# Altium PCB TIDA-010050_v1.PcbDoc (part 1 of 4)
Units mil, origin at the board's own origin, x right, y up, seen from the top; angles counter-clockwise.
Board outline 2060.77 x 1300 mil, 4 copper layers (Top Layer, signal1, signal2, Bottom Layer), stack 23.6 mil thick; 58 components, 30 nets, 158 pads, 41 vias.
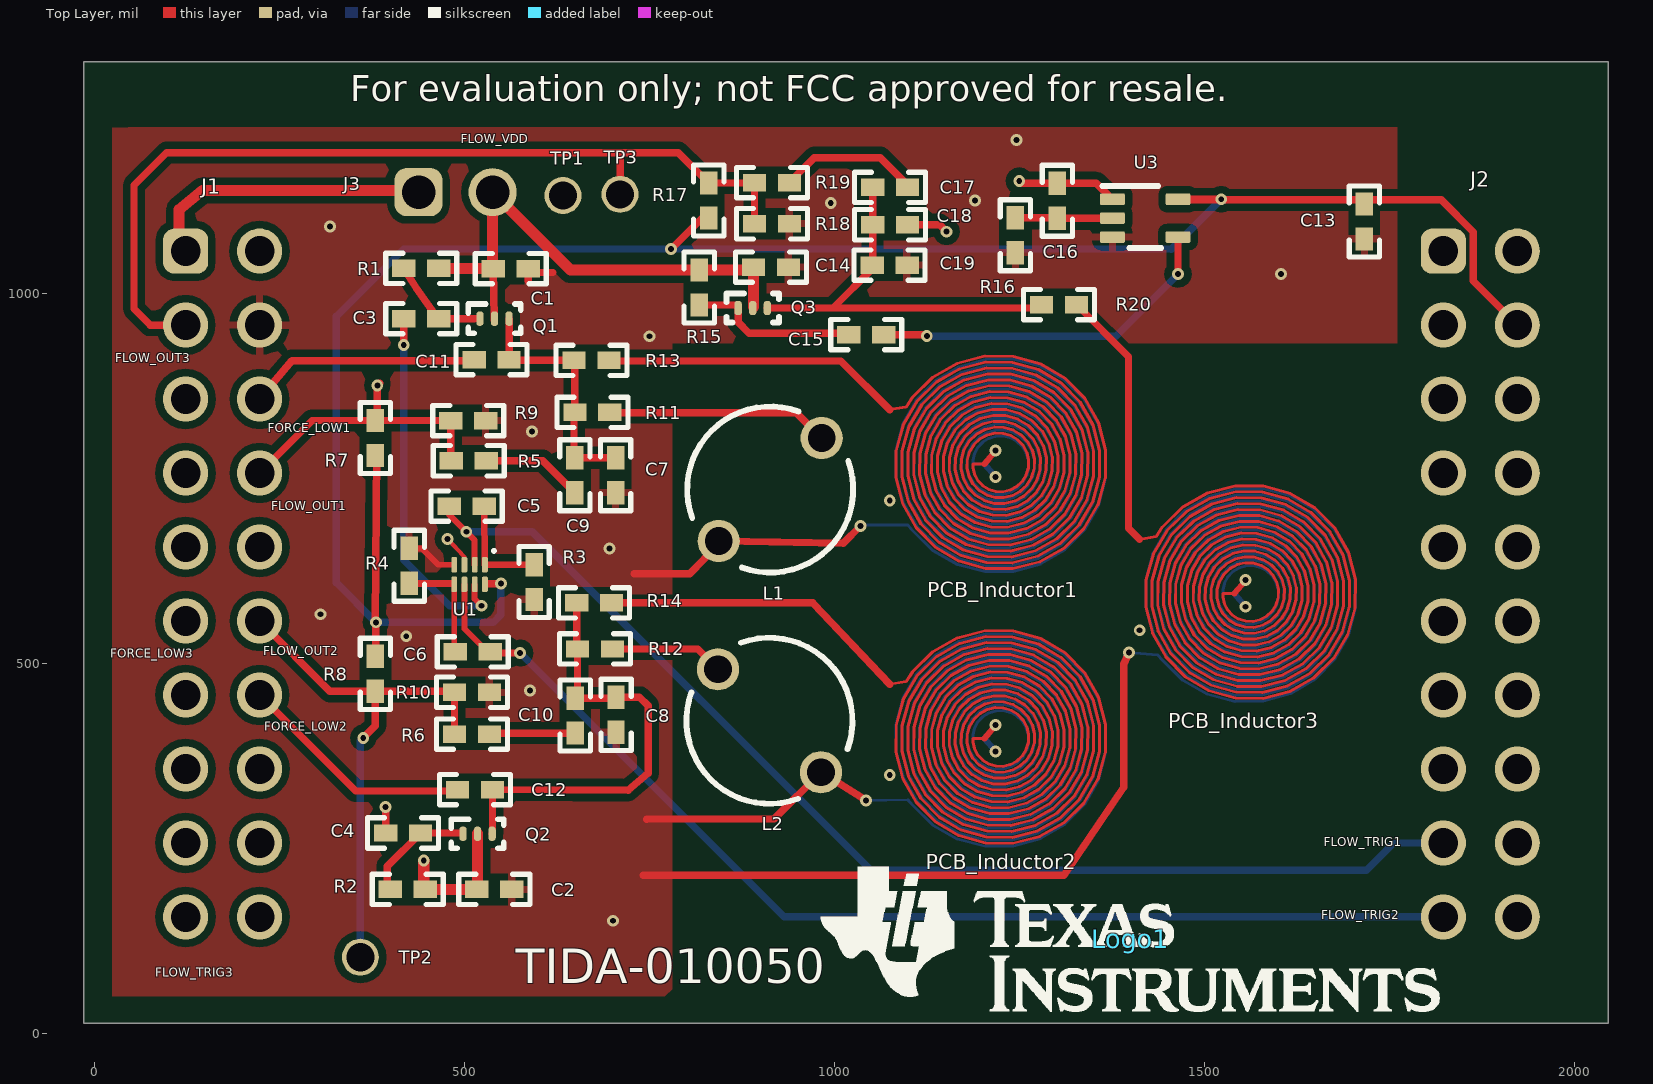
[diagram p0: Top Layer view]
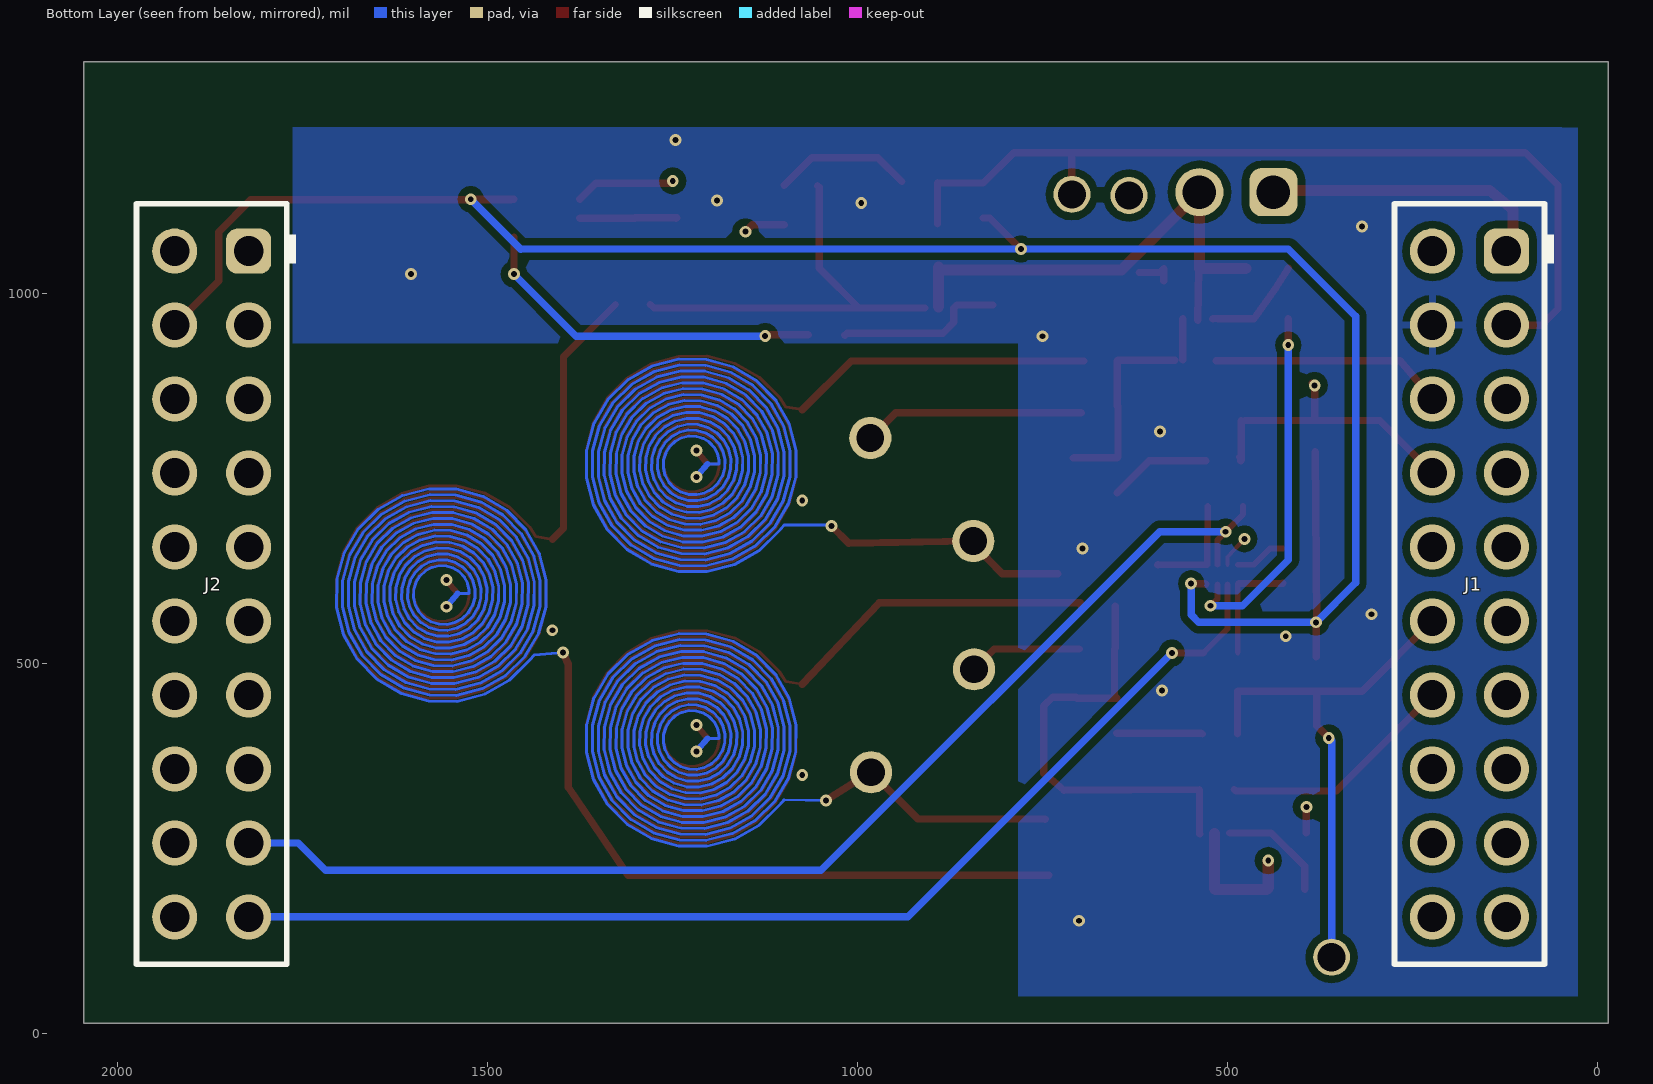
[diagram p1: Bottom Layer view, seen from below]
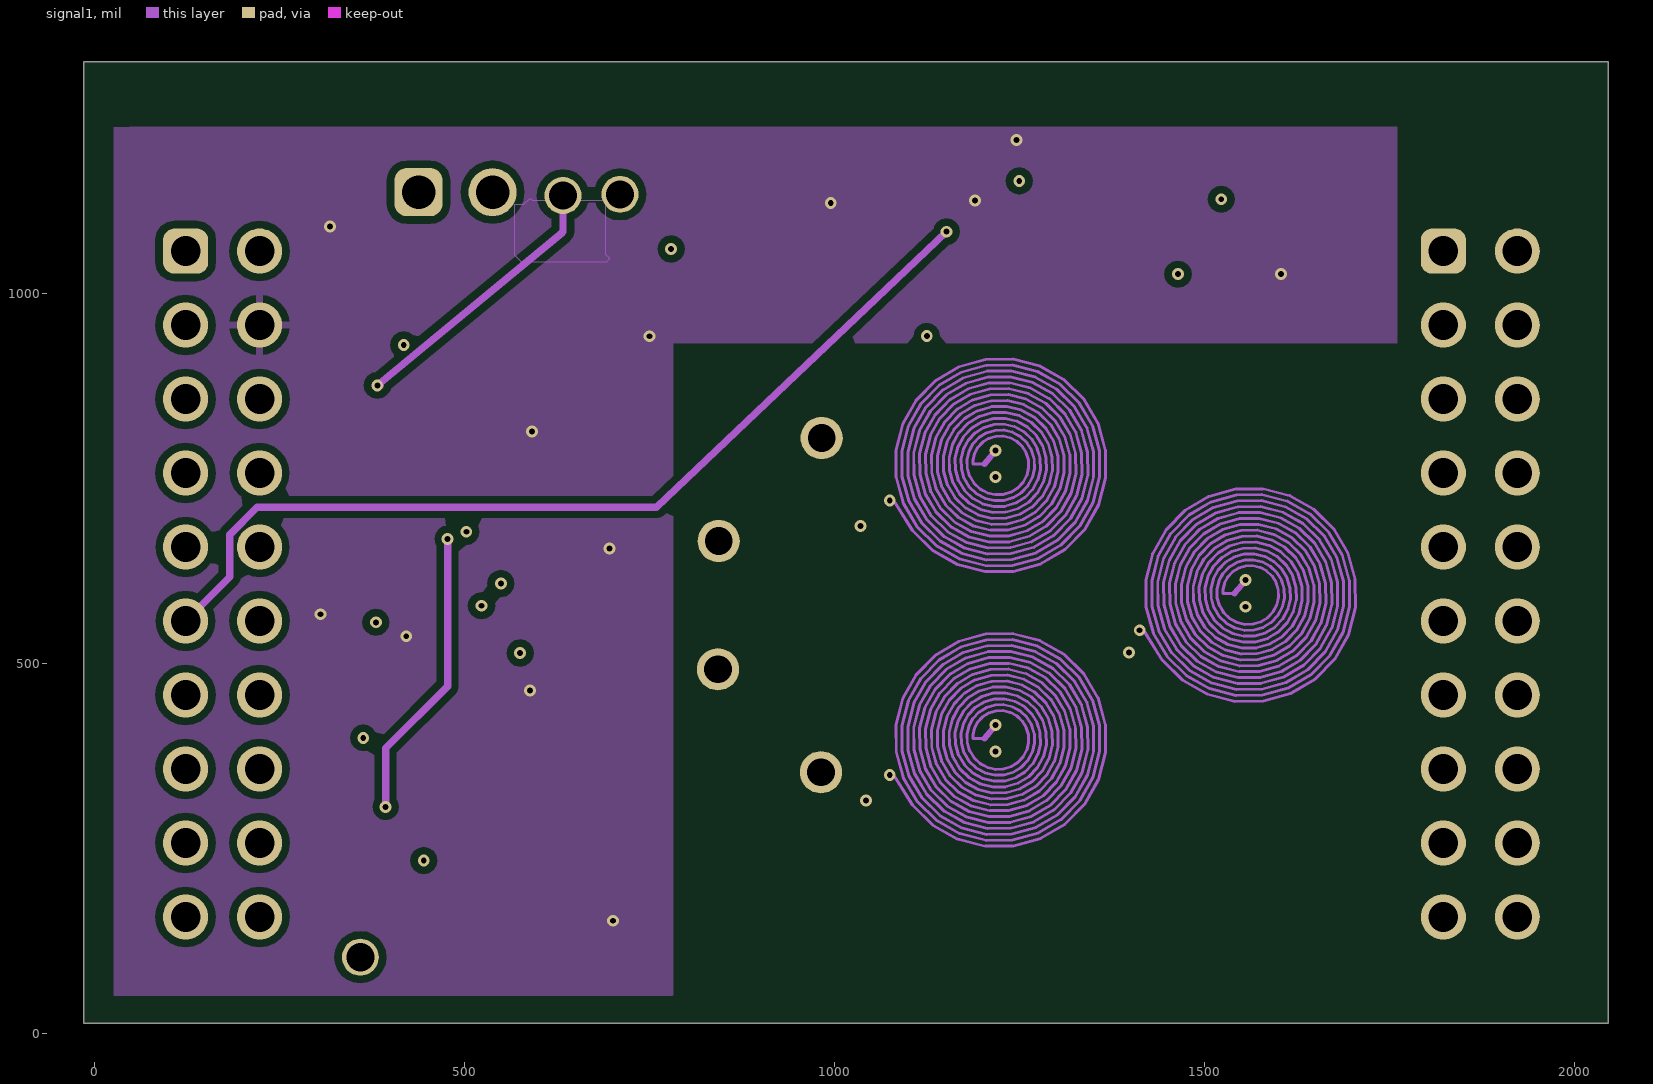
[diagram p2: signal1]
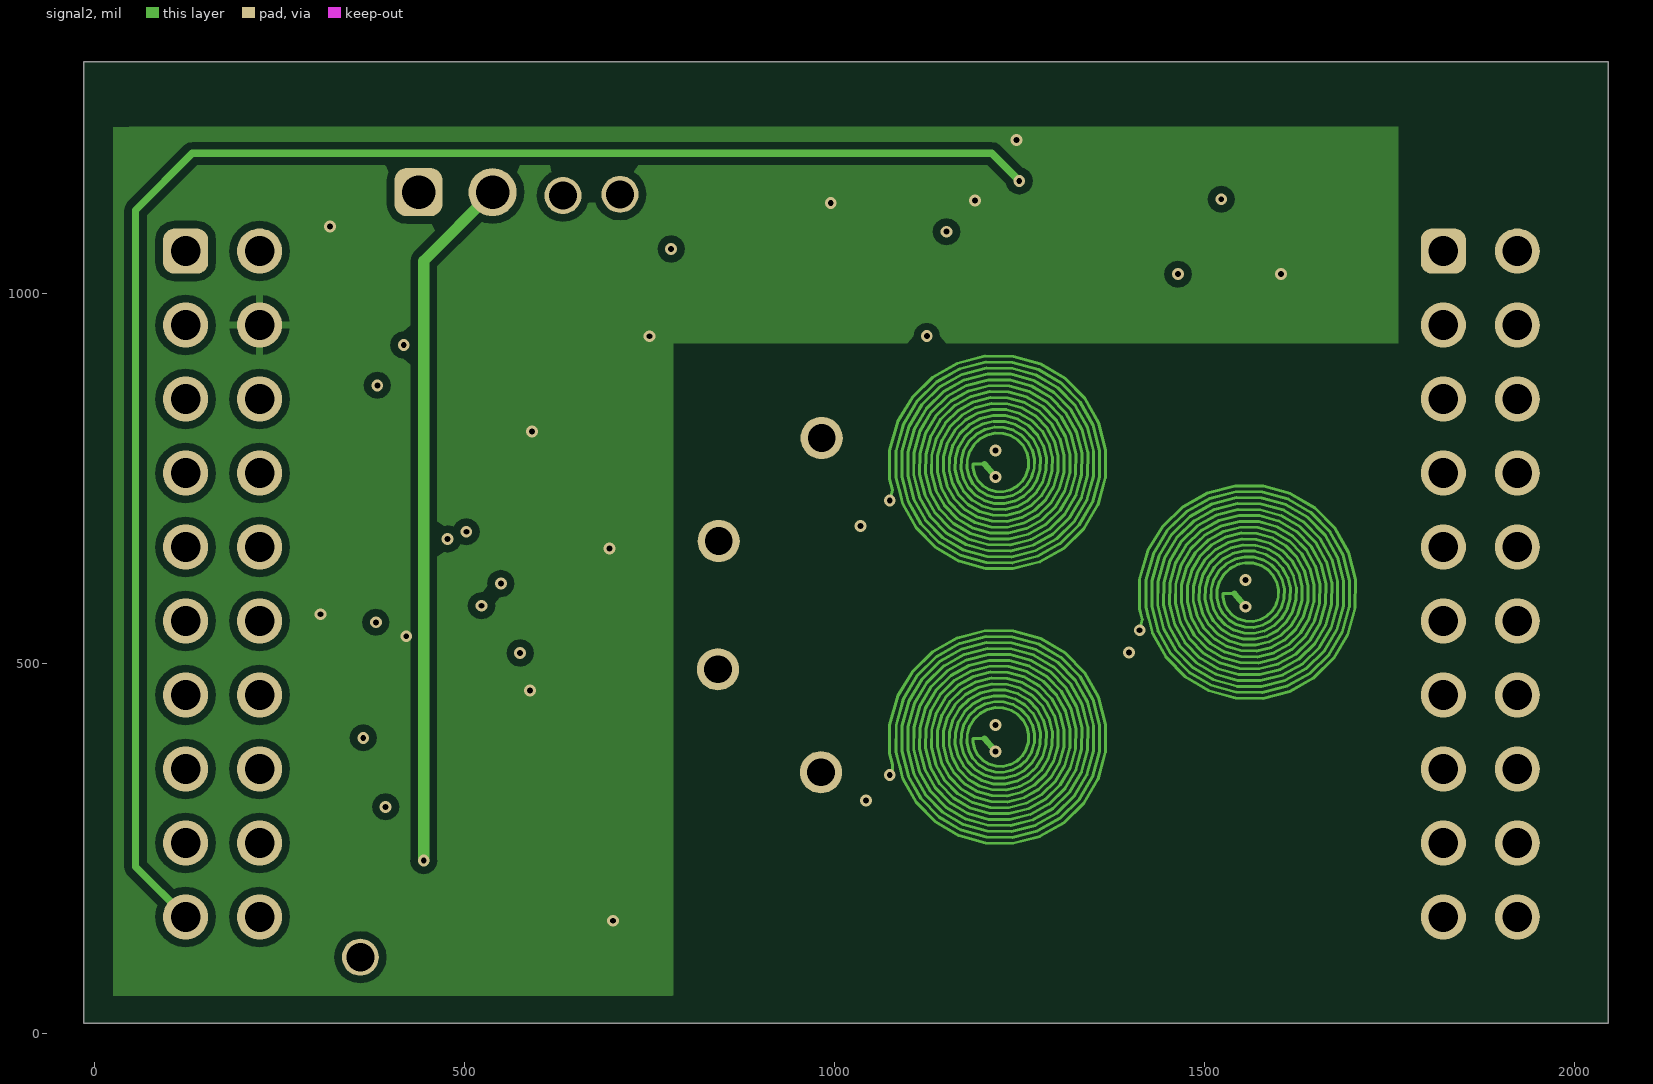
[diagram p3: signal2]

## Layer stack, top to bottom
Top Solder: solder mask 0.4, Solder Resist, Dk 3.5
Top Layer: signal copper 1.4
Dielectric 1: prepreg 5, FR-4, Dk 4.2
signal1: signal copper 1.4
Dielectric 2: core 8, FR-4, Dk 4.2
signal2: signal copper 1.4
Dielectric 3: prepreg 5, FR-4, Dk 4.2
Bottom Layer: signal copper 1.4
Bottom Solder: solder mask 0.4, Solder Resist, Dk 3.5

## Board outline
-15,13 2045.77,13 2045.77,1313 -15,1313

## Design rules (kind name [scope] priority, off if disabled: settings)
AcuteAngle [All] p1: minimum=4.50000000000000E+0001 checktracksonly=FALSE
AssemblyTestPointUsage [All] p1: valid=2
BoardOutlineClearance BoardOutlineClearance_MountingHoles [OnCopper and InComponentClass('Mounting Holes')] p1: gap=39.37 ignorepadtopadclearanceinfootprint=FALSE
BoardOutlineClearance BoardOutlineClearance_Poly [OnCopper and IsPoly] p2: gap=25 ignorepadtopadclearanceinfootprint=FALSE
BoardOutlineClearance [OnCopper and Not InComponentClass('Logo') and not InComponentClass('FiducialMark') and not InRegion(1000,500,4000,800) and not InPoly] p3: gap=30 ignorepadtopadclearanceinfootprint=FALSE
Clearance Clearance_Keepouts [((IsTrack Or IsArc) And Not InPoly) And IsFree and IsKeepOut vs ((IsTrack Or IsArc) And Not InPoly) And IsFree and IsKeepOut] p1: gap=0 ignorepadtopadclearanceinfootprint=FALSE
Clearance Clearance_Poly [InPolygon] p2: gap=10 ignorepadtopadclearanceinfootprint=TRUE
Clearance Clearance_FiducialMark [IsKeepOut and InComponentClass('FiducialMark') vs IsPad and InComponentClass('FiducialMark')] p3: gap=0 ignorepadtopadclearanceinfootprint=FALSE
Clearance [All] p4: gap=5 ignorepadtopadclearanceinfootprint=TRUE except(4: Arc-Arc Arc-Track Track-Track)
ComponentClearance ComponentClearance_MountingHoles_FiducialMarks [InComponentClass('Mounting Holes') vs InComponentClass('FiducialMark')] p1: gap=50 collisioncheckmode=3 verticalgap=10 showdistances=FALSE
ComponentClearance ComponentClearance_Shunt [InComponentClass('Header') vs InComponentClass('Shunt')] p2: gap=0 collisioncheckmode=3 verticalgap=0 showdistances=FALSE
ComponentClearance ComponentClearance_Logo [InComponentClass('Logo')] p3: gap=50 collisioncheckmode=3 verticalgap=10 showdistances=FALSE
ComponentClearance ComponentClearance_ScrewToNut [(HasFootprint('NY PMS 440 0025 PH')) vs (HasFootprint('Keystone_1902C'))] p4: gap=5 collisioncheckmode=3 verticalgap=10 showdistances=FALSE
ComponentClearance ComponentClearance_MountingHoles [InComponentClass('Mounting Holes')] p5: gap=250 collisioncheckmode=3 verticalgap=100000 showdistances=FALSE
ComponentClearance ComponentClearance_SmallPassives [HasFootprint('0201*') or HasFootprint('0402*') or HasFootprint('0508') or HasFootprint('0603*') or HasFootprint('0612') or HasFootprint('0805*') or HasFootprint('0815*') or HasFootprint('0830*') or HasFootprint('1206*') or HasFootprint('1210*') or HasFootprint('1808*') or HasFootprint('1812*') or HasFootprint('1825*') or HasFootprint('2010*') or HasFootprint('2220*') or HasFootprint('2225*') or HasFootprint('2512*') or HasFootprint('2728*') or HasFootprint('3518*') vs HasFootprint('0201*') or HasFootprint('0402*') or HasFootprint('0508') or HasFootprint('0603*') or HasFootprint('0612') or HasFootprint('0805*') or HasFootprint('0815*') or HasFootprint('0830*') or HasFootprint('1206*') or HasFootprint('1210*') or HasFootprint('1808*') or HasFootprint('1812*') or HasFootprint('1825*') or HasFootprint('2010*') or HasFootprint('2220*') or HasFootprint('2225*') or HasFootprint('2512*') or HasFootprint('2728*') or HasFootprint('3518*')] p6: gap=14.96 collisioncheckmode=3 verticalgap=10 showdistances=FALSE
ComponentClearance ComponentClearance_THtoSMT [IsThruComponent vs IsSMTComponent] p7: gap=40 collisioncheckmode=3 verticalgap=30 showdistances=FALSE
ComponentClearance ComponentClearance_THtoTH [IsThruComponent vs IsThruComponent] p8: gap=30 collisioncheckmode=3 verticalgap=30 showdistances=FALSE
ComponentClearance [All] p9: gap=30 collisioncheckmode=3 verticalgap=10 showdistances=FALSE
DiffPairsRouting [All] p1: maxlimit=100 minlimit=10 mostfreqgap=10 toplayer_minwidth=15 toplayer_maxwidth=15 toplayer_prefwidth=15 midlayer1_minwidth=15 midlayer1_maxwidth=15 midlayer1_prefwidth=15 midlayer2_minwidth=15 midlayer2_maxwidth=15 midlayer2_prefwidth=15 bottomlayer_minwidth=15 bottomlayer_maxwidth=15 bottomlayer_prefwidth=15 maxuncoupledlength=1000
FabricationTestPointUsage TestPointUsage [All] p1: valid=2 allowmultiple=FALSE
FabricationTestpoint Testpoint [All] p1: side=3 testpointundercomponent=TRUE minsize=40 maxsize=100 preferedsize=60 minholesize=0 maxholesize=40 preferedholesize=32 testpointgrid=1 allowsidetop=TRUE allowsidebottom=TRUE usegrid=TRUE gridtolerance=0.01
FanoutControl Fanout_LCC [IsLCC] p1: bgadir=Out bgaviamode=Centered fanoutstyle=Auto fanoutdirection=Alternating viagrid=1 // Fanout_LCC (Default Rule)
FanoutControl Fanout_BGA [IsBGA] p2: bgadir=Out bgaviamode=Centered fanoutstyle=Auto fanoutdirection=Alternating viagrid=1 // Fanout_BGA (Default Rule)
FanoutControl Fanout_Default [All] p4: bgadir=Out bgaviamode=Centered fanoutstyle=Auto fanoutdirection=Alternating viagrid=1 // Fanout_Default (Default Rule)
FanoutControl Fanout_Small [(CompPinCount < 5)] p5: bgadir=Out bgaviamode=Centered fanoutstyle=Auto fanoutdirection=OutThenIn viagrid=1 // Fanout_Small (Default Rule)
HoleSize [All] p1: absolutevalues=TRUE maxlimit=251 minlimit=7.87 maxpercent=80.000 minpercent=20.000
MinimumAnnularRing MinimumAnnularRing_ThermalPadVias [IsVia and InAnyComponent] p1: minimumring=4
MinimumAnnularRing [All] p2: minimumring=4
MinimumSolderMaskSliver MinimumSolderMaskSliver_Logo [InComponentClass('Logo') vs InComponentClass('Logo')] p1: minsoldermaskwidth=0.7
MinimumSolderMaskSliver [All] p2: minsoldermaskwidth=1
PlaneConnect [All] p1: planeconnectstyle=Relief reliefexpansion=10 reliefentries=4 reliefconductorwidth=10 reliefairgap=10
PolygonConnect "GND via" [IsVia] p1: connectstyle=Direct reliefconductorwidth=10 reliefentries=4 polygonreliefangle="90 Angle" airgapwidth=10
PolygonConnect PolygonConnect_1 [All] p2: connectstyle=Relief reliefconductorwidth=10 reliefentries=4 polygonreliefangle="90 Angle" airgapwidth=10
RoutingVias ThermalPadVias [IsVia and InAnyComponent] p1: holewidth=7.87 width=19.68 viastyle="Through Hole" minholewidth=7.87 minwidth=19.68 maxholewidth=12.99 maxwidth=23.62
RoutingVias [All] p2: holewidth=8 width=16 viastyle="Through Hole" minholewidth=8 minwidth=16 maxholewidth=8 maxwidth=16
SilkToBoardRegionClearance [Not ((IsComment or IsDesignator) And (Hide <> 'False')) and not InRegion(1000,500,4000,800)] p1:
SilkToSilkClearance SilkToSilkClearance_Pb-FreeLogo [(HasFootprint('Pb-Free_Overlay_Medium') OR HasFootprint('Pb-Free_Overlay_Small')) vs (HasFootprint('Pb-Free_Overlay_Medium') OR HasFootprint('Pb-Free_Overlay_Small'))] p1: silktosilkclearance=0
SilkToSilkClearance [All] p2: silktosilkclearance=0.1
SilkToSolderMaskClearance SilkToComponentPadClearance [(IsPad or IsFill or IsRegion) and InAnycomponent] p1: minsilkscreentomaskgap=0.1 clearancetoexposedcopper=TRUE
SilkToSolderMaskClearance "Silk to Solder Mask Opening" [All] p2: minsilkscreentomaskgap=0.1 clearancetoexposedcopper=FALSE
SolderMaskExpansion [All] p1: expansion=1.97
UnRoutedNet [All] p1: checkbadconnections=TRUE
Width [All] p1: maxlimit=100 minlimit=4.02 preferedwidth=10 checkconnectedcopper=TRUE
14 further rules are at their usual default settings.

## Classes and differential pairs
component class TIDA-010050_v1: C1 C2 C3 C4 C5 C6 C7 C8 C9 C10 C11 C12 C13 C14 C15 C16 C17 C18 C19 J1 J2 J3 L1 L2 Q1 Q2 Q3 R1 R2 R3 R4 R5 R6 R7 R8 R9 R10 R11 R12 R13 R14 R15 R16 R17 R18 R19 R20 TP1 TP2 TP3 U1 U3
component class Header: J3
component class Logo: Logo1
component class TIDA-010050_v1_Hardware: Logo1 Logo3 ZZ1 ZZ2 ZZ3 ZZ4
component class AssemblyNote: ZZ1 ZZ2 ZZ3 ZZ4

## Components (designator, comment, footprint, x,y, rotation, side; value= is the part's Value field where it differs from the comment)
C1 "GRM155C81A105KA12D" 0402 562.35,1033.33 r0 top value=1uF
C2 "GRM155C81A105KA12D" 0402 540.08,194.14 r0 top value=1uF
C3 "GRM155R71H681KA01D" 0402 441.28,965.7 r0 top value=680pF
C4 "GRM155R71H681KA01D" 0402 416.76,270.45 r0 top value=680pF
C5 "GRM1555C1H101JA01D" 0402 502.66,712.21 r0 top value=100pF
C6 "GRM1555C1H101JA01D" 0402 510.82,515.23 r180 top value=100pF
C7 "GRM1555C1H391JA01D" 0402 703.91,754 r270 top value=390pF
C8 "GRM1555C1H391JA01D" 0402 704.53,430.15 r270 top value=390pF
C9 "GRM1555C1H101JA01D" 0402 648.99,754 r90 top value=100pF
C10 "GRM1555C1H101JA01D" 0402 649.53,429.15 r90 top value=100pF
C11 "GRM1555C1H101JA01D" 0402 536.36,910.31 r180 top value=100pF
C12 "GRM1555C1H101JA01D" 0402 513.98,329.21 r180 top value=100pF
C13 "GRM155R61H102KA01D" 0402 1716,1097 r270 top value=1000pF
C14 "GRM155C81A105KA12D" 0402 914.11,1035.43 r0 top value=1uF
C15 "GRM155R71H681KA01D" 0402 1042.78,944.05 r180 top value=680pF
C16 "GRM1555C1H101JA01D" 0402 1301.03,1125.05 r270 top value=100pF
C17 "GRM1555C1H101JA01D" 0402 1075,1143.02 r180 top value=100pF
C18 "GRM1555C1H101JA01D" 0402 1075,1092.5 r0 top value=100pF
C19 "GRM1555C1H391JA01D" 0402 1074.38,1038 r0 top value=390pF
J1 "SSQ-110-23-L-D" Samtec_SSQ-110-23-x-D 172.8,607 r270 bottom
J2 "SSQ-110-23-L-D" Samtec_SSQ-110-23-x-D 1872.81,607 r270 bottom
J3 "61300211121" WURTH_61300211121 487.63,1136.63 r0 top
L1 "GT1128-0" GT1128-0 912.92,734.7 r45 top value=235uH
L2 "GT1128-0" GT1128-0 911.92,422.13 r135 top value=235uH
Logo1 "Texas Instruments" TI_Stacked_Overlay_Small 1399.34,127 r0 top
Logo3 "FCC disclaimer" FCC_disclaimer 2879,1407 r0 top
Q1 "CSD23285F5" YJK0003A 540.3,965.63 r0 top value=-12V
Q2 "CSD23285F5" YJK0003A 517.38,269.45 r0 top value=-12V
Q3 "CSD23285F5" YJK0003A 889.33,980 r0 top value=-12V
R1 "CRCW040247K0JNED" 0402 441.3,1033.56 r0 top value=47k
R2 "CRCW040247K0JNED" 0402 423.04,194.14 r0 top value=47k
R3 "CRCW04021K00JNED" 0402 593.91,609.59 r90 top value=1.0k
R4 "CRCW04021K00JNED" 0402 425.05,631.59 r270 top value=1.0k
R5 "CRCW0402470RJNED" 0402 505.4,773.64 r180 top value=470
R6 "CRCW0402470RJNED" 0402 509.91,404.19 r180 top value=470
R7 "CRCW0402330KJNED" 0402 379.31,804.43 r270 top value=330k
R8 "CRCW0402330KJNED" 0402 379.31,485.59 r90 top value=330k
R9 "CRCW0402330KJNED" 0402 504.85,827.92 r180 top value=330k
R10 "CRCW0402330KJNED" 0402 509.91,460.59 r180 top value=330k
R11 "MCR01MZPJ000" 0402 672.61,838.94 r180 top value=0
R12 "MCR01MZPJ000" 0402 676.15,519.16 r180 top value=0
R13 "MCR01MZPJ000" 0402 671.44,909.21 r180 top value=0
R14 "MCR01MZPJ000" 0402 674.92,581.54 r180 top value=0
R15 "CRCW040247K0JNED" 0402 816.95,1007.67 r90 top value=47k
R16 "CRCW04021K00JNED" 0402 1244.32,1078.48 r90 top value=1.0k
R17 "CRCW0402330KJNED" 0402 829.82,1125.38 r270 top value=330k
R18 "CRCW0402330KJNED" 0402 915.28,1094 r180 top value=330k
R19 "CRCW0402470RJNED" 0402 915.28,1149.66 r180 top value=470
R20 "MCR01MZPJ000" 0402 1303.32,984.74 r180 top value=0
TP1 "FLOW_OUT1" TESTPOINT#1 632.83,1132 r0 top
TP2 "FLOW_OUT2" TESTPOINT#2 359,102.56 r0 top
TP3 "FLOW_OUT2" TESTPOINT#2 710,1133.71 r0 top
U1 "SN74AUP2G00DQER" DQE0008A_V 506.6,619.78 r270 top
U3 "SN74AUP1T00DCKR" DCK0005A_N 1419.79,1101.42 r0 top
ZZ1 "This Assembly Note is for PCB labels only" AssemblyNoteLabel 185,3938 r0 top
ZZ2 "These assemblies are ESD sensitive, ESD precautions shall be observed." AssemblyNote 185,3829.11 r0 top
ZZ3 "These assemblies must be clean and free from flux and all contaminants. Use of no clean flux is not acceptable." AssemblyNote 185,3740.56 r0 top
ZZ4 "These assemblies must comply with workmanship standards IPC-A-610 Class 2, unless otherwise specified." AssemblyNote 185,3652 r0 top

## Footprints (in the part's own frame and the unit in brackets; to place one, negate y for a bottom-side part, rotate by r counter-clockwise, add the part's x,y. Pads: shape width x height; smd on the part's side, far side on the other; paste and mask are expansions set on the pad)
0402 [mm] "0402 from SM-752 data"
  rect 0.8x0.6 smd: 1(-0.6,0) 2(0.6,0)
  silkscreen extent -1.22,-0.52 1.22,0.52, body extent -0.55,-0.3 0.55,0.3, height 0.6
AssemblyNote [mil] "Assembly Note"
AssemblyNoteLabel [mil] "Assembly Note for PCB Labels"
DCK0005A_N [mm] "SOT353, 5-Leads, Body 2x1.3mm, Pitch 0.65mm, Lead Span 2.1mm, IPC Medium Density"
  rrect25% 0.85x0.4 smd: 1(-1.125,0.65) 2(-1.125,0) 3(-1.125,-0.65) 4(1.125,-0.65) 5(1.125,0.65)
  silkscreen extent -1.48,-1.02 0.55,1.1, body extent -1.14,-1 1.14,1, height 0.95
DQE0008A_V [mm] "SON, 8-Leads, Body 1.4x1mm, Pitch 0.35mm, TI Recommend"
  rrect50% 0.53x0.2 smd paste-0.5: 1(-0.335,0.525) 2(-0.335,0.175) 3(-0.335,-0.175) 4(-0.335,-0.525) 5(0.335,-0.525) 6(0.335,-0.175) 7(0.335,0.175) 8(0.335,0.525)
  silkscreen extent -0.86,0.79 -0.76,0.89, body extent -0.5,-0.7 0.5,0.7, height 0.4
FCC_disclaimer [mil]
GT1128-0 [mm] "TH, 2-Leads, Body 6.4x5.7mm, Pin Spacing 5mm"
  round 1.45 hole 0.95: 1(-2.5,0) 2(2.5,0)
  silkscreen extent -2.58,-2.85 2.58,2.85, body extent -2.85,-2.85 2.85,2.85, height 6.2
Samtec_SSQ-110-23-x-D [mm] "Receptacle, 2.54mm, 10x2, TH"
  rrect50% 1.55x1.55 hole 1.02: 1(-11.43,1.27)
  round 1.55 hole 1.02: 2(-11.43,-1.27) 3(-8.89,1.27) 4(-8.89,-1.27) 5(-6.35,1.27) 6(-6.35,-1.27) 7(-3.81,1.27) 8(-3.81,-1.27) 9(-1.27,1.27) 10(-1.27,-1.27) 11(1.27,1.27) 12(1.27,-1.27) 13(3.81,1.27) 14(3.81,-1.27) 15(6.35,1.27) 16(6.35,-1.27) 17(8.89,1.27) 18(8.89,-1.27) 19(11.43,1.27) 20(11.43,-1.27)
  silkscreen extent -13.05,-2.58 13.05,2.9, body extent -12.95,-2.48 12.95,2.48, height 8.51
TESTPOINT#1 [mm]
  round 1.27 hole 0.95: 1(0,0)
TESTPOINT#2 [mm]
  round 1.27 hole 0.965: 1(0,0)
TI_Stacked_Overlay_Small [mil]
  silkscreen extent -418,-98 418,98
WURTH_61300211121 [mm] "Header, 2.54mm, 2x1, TH"
  rrect50% 1.65x1.65 hole 1.15: 1(-1.27,0)
  round 1.65 hole 1.15: 2(1.27,0)
  body extent -2.54,-1.27 2.54,1.27, height 8.54
YJK0003A [mm] "SMD, 3-Leads, Body 1.49x0.73mm"
  rrect50% 0.2x0.39 on Top Paste: 1(-0.525,0) 2(0,0) 3(0.525,0)
  rrect80% 0.25x0.49 smd paste-0.15 mask-0.05: 1(-0.5,0) 2(0,0) 3(0.5,0)
  silkscreen extent -0.9,-0.5 0.9,0.5, body extent -0.75,-0.37 0.74,0.36, height 0.35

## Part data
C1 C2 C14: library part CMP-0064971-2, "CAP, CERM, 1 uF, 10 V,+/- 10%, X6S, 0402", Cap_Case=0402, Manufacturer=MuRata, Supplier Part Number 1=490-12699-1-ND, TempCo=X6S, Tolerance_%=10%, Value1=Unknown, Value2=10V, ValueDisplayed=1uF
C3 C4 C15: library part CMP-0006695-1, "CAP, CERM, 680 pF, 50 V, +/- 10%, X7R, 0402", Cap_Case=0402, Manufacturer=MuRata, Supplier Part Number 1=490-1302-1-ND, TempCo=X7R, Tolerance_%=10%, Value1=Unknown, Value2=50V, ValueDisplayed=680pF
C5 C6 C9 C10 C11 C12 C16 C17 C18: library part CMP-0006410-1, "CAP, CERM, 100 pF, 50 V, +/- 5%, C0G/NP0, 0402", Cap_Case=0402, Manufacturer=MuRata, Supplier Part Number 1=81-GRM1555C1H101JA1D, TempCo=C0G/NP0, Tolerance_%=5%, Value1=Unknown, Value2=50V, ValueDisplayed=100pF
C7 C8 C19: library part CMP-0006459-2, "CAP, CERM, 390 pF, 50 V, +/- 5%, C0G/NP0, 0402", Cap_Case=0402, Manufacturer=MuRata, Supplier Part Number 1=490-1296-1-ND, TempCo=C0G/NP0, Tolerance_%=5%, Value1=Unknown, Value2=50V, ValueDisplayed=390pF
C13: library part CMP-0006613-1, "CAP, CERM, 1000 pF, 50 V, +/- 10%, X5R, 0402", Cap_Case=0402, Manufacturer=MuRata, Supplier Part Number 1=GRM155R61H102KA01D-ND, TempCo=X5R, Tolerance_%=10%, Value1=Unknown, Value2=50V, ValueDisplayed=1000pF
J1 J2: library part CMP-0055702-1, "Receptacle, 2.54mm, 10x2, Gold, TH", Color=Black, Current_A=6.3A, Manufacturer=Samtec, Voltage_V=550V
J3: library part CMP-0054794-2, "Header, 2.54 mm, 2x1, Gold, TH", Color=Black, Manufacturer="Wurth Elektronik", Supplier Part Number 1=732-5315-ND
L1 L2: library part CMP-0062040-1, "Inductor, 235uH, TH", Manufacturer="Gemphil Technologies", Value2=A, ValueDisplayed=150uH
Logo1: library part CMP-0074838-1, "Texas Instrument Corporate Signature"
Logo3: library part CMP-0074847-1, "FCC_disclaimer"
Q1 Q2 Q3: library part CMP-0000021-3, "MOSFET, P-CH, -12 V, -3.3 A, YJK0003A (PICOSTAR-3)", Alternate Manufacturer=None, Manufacturer="Texas Instruments", Value1=0.03, Value2="3.2 nC"
R1 R2 R15: library part CMP-0026935-1, "RES, 47 k, 5%, 0.063 W, 0402", Manufacturer=Vishay-Dale, Power_W=63mW, Supplier Part Number 1=541-47KJCT-ND, TempCo="200 ppm/C", Tolerance_%=5%, Value2=0.063W, Value_Code=47k0, ValueDisplayed=47k
R3 R4 R16: library part CMP-0026852-1, "RES, 1.0 k, 5%, 0.063 W, 0402", Manufacturer=Vishay-Dale, Power_W=63mW, Supplier Part Number 1=541-1.0KJCT-ND, TempCo="200 ppm/C", Tolerance_%=5%, Value2=0.063W, Value_Code=1k00, ValueDisplayed=1.0k
R5 R6 R19: library part CMP-0026934-1, "RES, 470, 5%, 0.063 W, 0402", Manufacturer=Vishay-Dale, Power_W=63mW, Supplier Part Number 1=541-470JCT-ND, TempCo="200 ppm/C", Tolerance_%=5%, Value2=0.063W, Value_Code=470R, ValueDisplayed=470
R7 R8 R9 R10 R17 R18: library part CMP-0026905-1, "RES, 330 k, 5%, 0.063 W, 0402", Manufacturer=Vishay-Dale, Power_W=63mW, Supplier Part Number 1=541-330KJCT-ND, TempCo="200 ppm/C", Tolerance_%=5%, Value2=0.063W, Value_Code=330k
R11 R12 R13 R14 R20: library part CMP-0027002-2, "RES, 0, 5%, 0.063 W, 0402", Manufacturer=Rohm, Power_W=63mW, Supplier Part Number 1=RHM0.0JCT-ND, TempCo="500 ppm/C", Tolerance_%=5%, Value2=0.063W, Value_Code=0000, ValueDisplayed=0
TP1 TP2 TP3: library part CMP-0078143-2, "TEST POINT.  No entry in BOM.", Manufacturer=N/A
U1: library part CMP-0051930-1, "Low-Power Dual 2-Input Positive-NAND Gate, DQE0008A, LARGE T&R", F @ Nom Voltage(Max)(Mhz)=100, Generic Part Number=SN74AUP2G00, ICC @ Nom Voltage(Max)(mA)=0.0009, Manufacturer="Texas Instruments", Operating Temperature Range(C)="-40 to 85", Rating=Catalog, tpd @ Nom Voltage(Max)(ns)=31.8,26.3,16.6,12.9,8.8,6.7, Voltage(Nom)(V)=0.8,1.2,1.5,1.8,2.5,3.3
U3: library part CMP-0051743-2, "Low Power, 1.8/2.5/3.3-V In, 3.3-V CMOS Out, Single 2-Input Positive-NAND Gate, DCK0005A, LARGE T&R", F @ Nom Voltage(Max)(Mhz)=190, Generic Part Number=SN74AUP1T00, ICC @ Nom Voltage(Max)(mA)=0.0009, Manufacturer="Texas Instruments", Operating Temperature Range(C)="-40 to 85", Rating=Catalog, tpd @ Nom Voltage(Max)(ns)=9.8,8.5,7.8, Voltage(Nom)(V)=1.8,2.5,3.3
ZZ1: library part CMP-0003616-3
ZZ2: library part CMP-0077236-1
ZZ3: library part CMP-0077237-1
ZZ4: library part CMP-0077238-1

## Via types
v1: diameter 16, hole 8, Top Layer to Bottom Layer, 40 vias
v2: diameter 16/16/16/16 (per signal layer), hole 8, Top Layer to Bottom Layer, 1 vias

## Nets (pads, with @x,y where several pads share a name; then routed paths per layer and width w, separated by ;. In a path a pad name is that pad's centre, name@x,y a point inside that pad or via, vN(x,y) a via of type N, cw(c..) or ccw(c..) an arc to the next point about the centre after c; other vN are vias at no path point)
3.3V: J1.1 J3.1 | length 377.2
  Top Layer w15: J1.1@114,1057 114,1113 145.48,1139 J3.1@425.83,1139
FLOW_BIAS: C13.1 J2.4 R7.2 R8.2 R17.2 U1.8 U3.5 | length 2902
  Top Layer w10: R8.2@379.91,508.4 v1(379.91,555.21) 378.91,556.21 R7.2@380.92,785.95 ; U1.8@528.91,606.59 529.92,607.6 v1(548.91,607.6) ; v1(779,1059.81) 820.94,1101.76 R17.2@829.82,1101.76 ; U3.5@1464.08,1127.02 v1(1522.6,1127.02) ; U3.5@1468,1126.22 1819.82,1126.22 1863.32,1082.72 1863.32,1016.49 J2.4@1922.81,957
  Bottom Layer w10: v1(548.91,607.6) 548.91,565.24 538.88,555.21 v1(379.91,555.21) 326.66,608.45 326.66,969 417.47,1059.81 v1(779,1059.81) 1454.37,1059.81 1454.89,1059.3 v1(1522.6,1127.02)
FLOW_OUT1: J1.8 R5.2 R7.1 R9.2 TP1.1 | length 783.7
  Top Layer w10: J1.8@222.8,757 293.8,828 R7.1@379.31,828.05 ; v1@385,878.61 v1(381.91,875.52) 381.91,830.65 R7.1@379.31,828.05 ; R9.2@476.61,828.05 R7.1@379.31,828.05 ; R9.2@481.23,827.92 481.23,774.19 R5.2@481.78,773.64 ; R5.2@482.69,779.29 R5.2@483.39,778.6
  signal1 w10: v1@385.63,875.52 v1(381.91,875.52) 632,1082.19 632.83,1083.02 TP1.1@632.83,1132 TP1.1@632.83,1133
  signal2 w10: J1.8@214,757 J1.8@223,748
FLOW_OUT2: J1.12 R6.2 R8.1 R10.2 TP2.1 | length 728.3
  Top Layer w10: J1.12@222.8,557 317.84,461.96 R8.1@379.31,461.96 ; v1(362.91,399) 379.31,415.4 R8.1@379.31,461.96 ; R6.2@486.28,404.19 486.28,461.71 486.03,461.96 R8.1@379.31,461.96
  Bottom Layer w10: TP2.1@359,102.56 359,395.09 v1(362.91,399)
FLOW_OUT3: J1.3 R17.1 R18.2 R19.2 TP3.1 | length 1232.8
  Top Layer w10: J1.3@122.8,957 75,957 53,979 53,1146 97,1190 708,1190 ; TP3.1@710,1133.71 710,1188 708,1190 ; R18.2@891.66,1094 R19.2@891.66,1149.66 891,1149 R17.1@829.82,1149 788.82,1190 708,1190
FLOW_TRIG1: C5.1 J2.17 U1.2 | length 1619
  Top Layer w8: C5.1@479.04,712.21 479.04,700.73 v1(502.17,677.61) 513.49,666.28 U1.2@513.49,632.97
  Bottom Layer w10: v1(502.17,677.61) 591.57,677.61 1049.17,220 1718.91,220 1755.91,257 J2.17@1822.81,257
FLOW_TRIG2: C6.1 J2.19 U1.6 | length 1535.7
  Top Layer w8: U1.6@499.71,606.59 499.71,546.53 C6.1@532.53,513.71
  Top Layer w10: C6.1@532.53,513.71 v1(574.91,513.71)
  Bottom Layer w10: v1(574.91,513.71) 931.61,157 J2.19@1814,157
FLOW_TRIG3: C16.1 J1.19 U3.1 | length 2361.2
  Top Layer w10: v1(1249.6,1151.8) 1252.73,1148.67 C16.1@1301.03,1148.67 1353.85,1148.67 U3.1@1375.5,1127.02
  signal2 w10: J1.19@122.8,157 55,224.8 55,1112 132,1189 1212.4,1189 v1(1249.6,1151.8)
FLOW_VDD: C1.1 C2.1 C14.1 J3.2 Q1.2@540.3,965.63 Q2.2@517.38,269.45 Q3.2@889.33,980 R1.2 R2.2 R15.2 | length 1817
  Top Layer w10: C1.1@538.72,1033.33 539.96,965.62 Q1.2@540,963.4 ; C14.1@886.35,1031.29 C14.1@890.49,1035.43 ; Q3.2@889.33,980 Q3.2@890.49,981.16
  Top Layer w15: v1(444.66,233.21) 444.66,196.14 R2.2@446.66,194.14 C2.1@516.45,194.14 517.38,195.07 Q2.2@517.38,269.45 ; R1.2@475.1,1033.56 537.63,1033.56 537.63,1073.06 J3.2@537.63,1136.63 642.96,1031.29 R15.2@816.95,1031.29 C14.1@886.35,1031.29 ; Q3.2@890.49,981.16 C14.1@890.49,1035.43
  signal2 w15: v1(444.66,233.21) 444.66,1043.66 J3.2@537.63,1136.63
FORCE_LOW1: C11.2 J1.6 | length 320.6
  Top Layer w10: J1.6@211.85,858.79 J1.6@216.39,858.79 ; J1.6@222.8,857 266.6,909 C11.2@514.71,909
FORCE_LOW2: C12.2 J1.14 | length 322.1
  Top Layer w10: J1.14@222.8,457 352.59,327.21 488.36,327.21 C12.2@490.36,329.21
FORCE_LOW3: C18.2 J1.11 | length 1330.7
  Top Layer w10: C18.2@1098.62,1092.5 1130.59,1092.5 1141.9,1092.5 v1(1151.18,1083.22)
  signal1 w10: J1.11@122.8,557 182.29,616.49 182.29,673.78 219.51,711 759.31,711 v1(1151.18,1083.22)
